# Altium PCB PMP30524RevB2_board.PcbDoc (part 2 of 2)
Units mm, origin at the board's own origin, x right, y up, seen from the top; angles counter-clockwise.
Board outline 60.96 x 53.34 mm, 2 copper layers (Top Layer, Bottom Layer), stack 1.575 mm thick; 66 components, 30 nets, 147 pads, 87 vias.
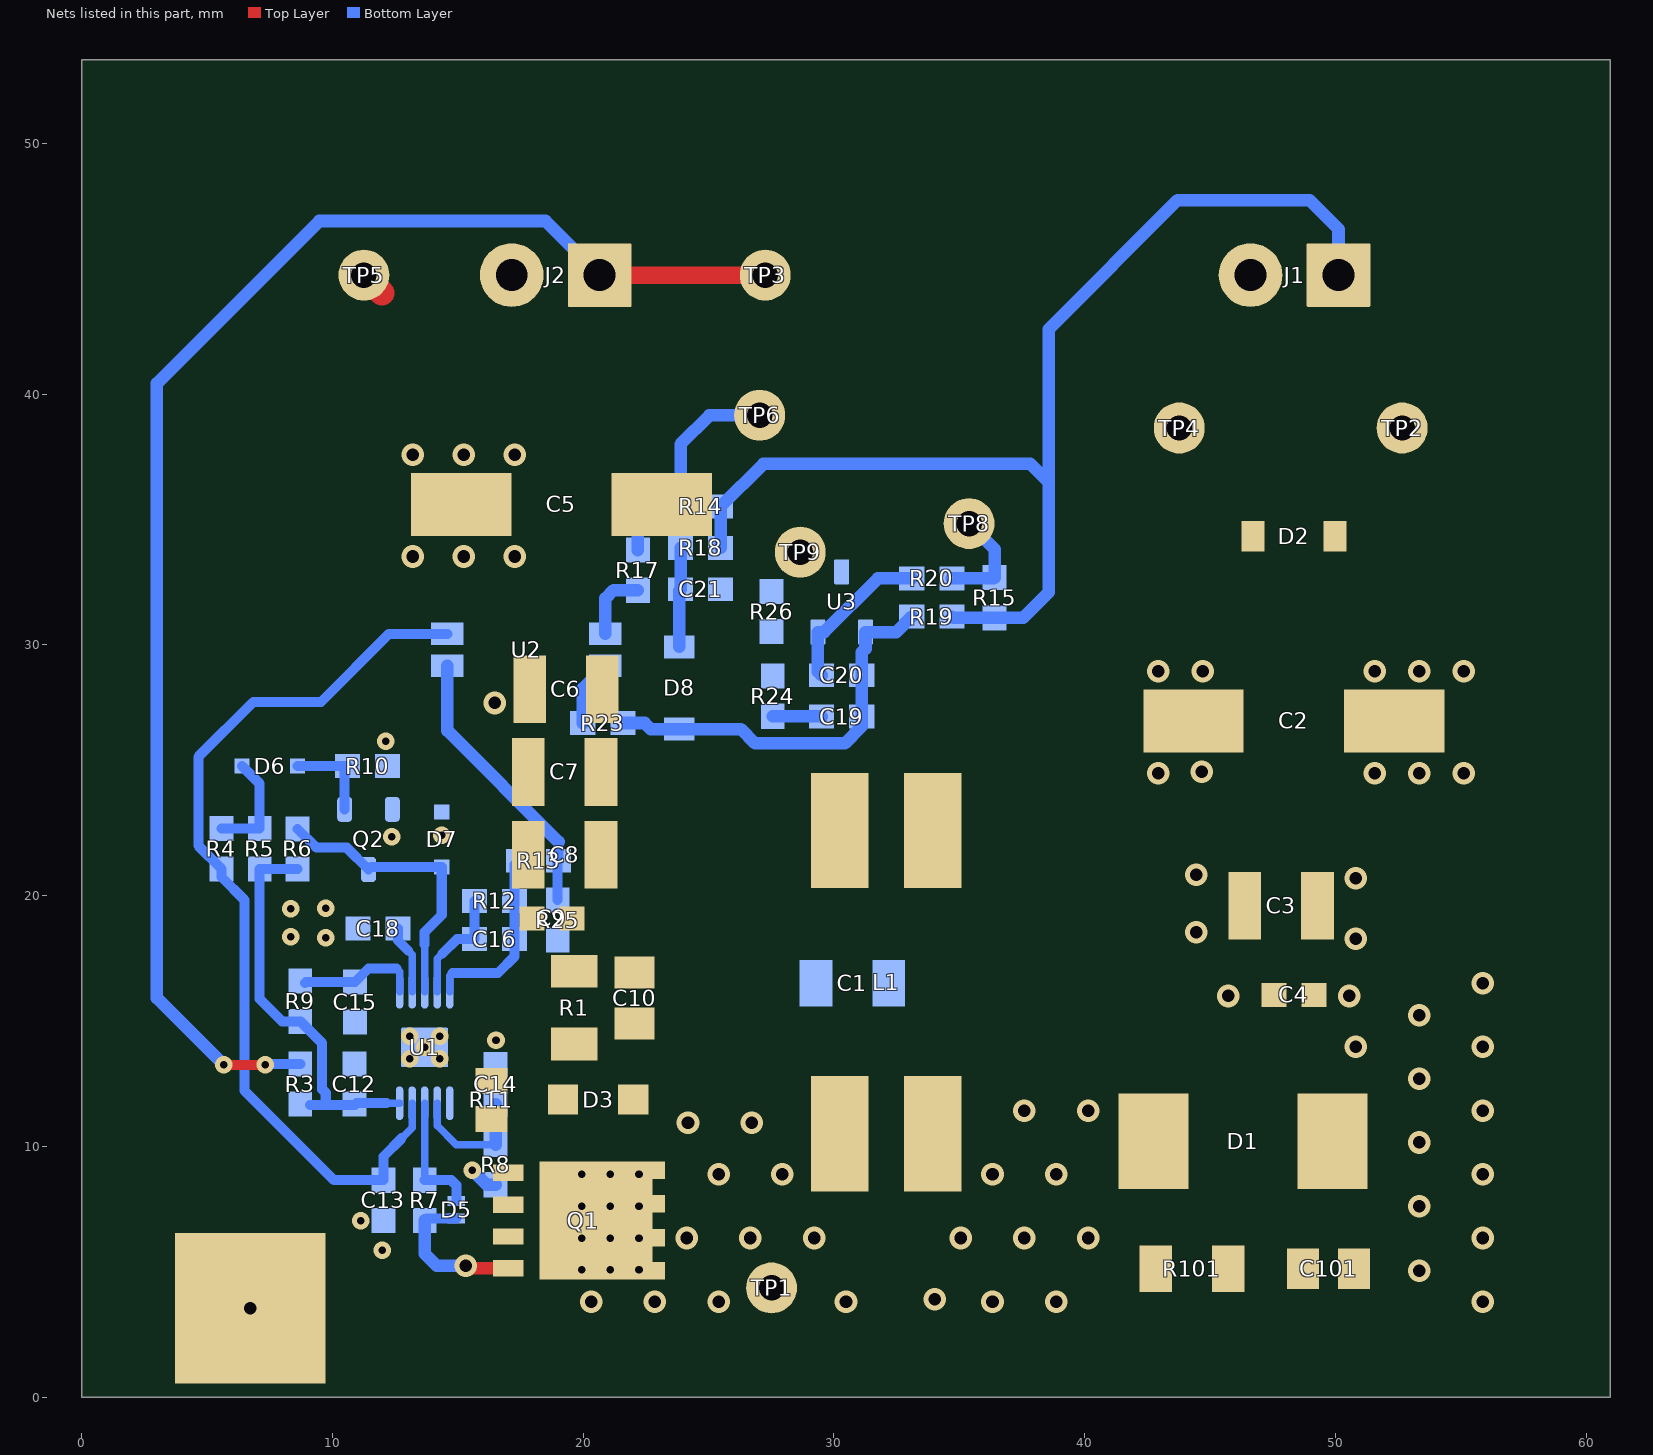
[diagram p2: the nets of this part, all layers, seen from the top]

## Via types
v1: diameter 0.9, hole 0.5, Top Layer to Bottom Layer, 28 vias
v2: diameter 0.9, hole 0.5, Top Layer to Bottom Layer, tented top, 27 vias
v3: diameter 0.7, hole 0.3, Top Layer to Bottom Layer, 20 vias
v4: diameter 0.7, hole 0.3, Top Layer to Bottom Layer, tented bottom, 10 vias
v5: diameter 0.9, hole 0.5, Top Layer to Bottom Layer, tented bottom, 2 vias

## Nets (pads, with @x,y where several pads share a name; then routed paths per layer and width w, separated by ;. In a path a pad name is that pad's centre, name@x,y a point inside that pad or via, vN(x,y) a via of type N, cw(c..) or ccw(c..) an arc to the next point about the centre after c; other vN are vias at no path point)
GND: C1.2 C5.2 C6.2 C7.2 C8.2 C9.2 C12.2 C13.2 C14.2 C15.2 C18.2 D7.2 J2.2 pad.1 Q2.2 R10.1 R11.1 R25.1 TP5.1 U1.6 U1.11 | length 1
  Top Layer w1: TP5.1@11.257,44.748 TP5.1@11.972,44.033
  other v1: 16.466,27.686 13.208,33.528 13.208,37.592 15.24,37.592 17.272,37.592
  other v3: 11.985,5.857 13.078,13.501 14.278,13.501 13.678,13.951 13.078,14.401 14.278,14.401
  other v4: 11.13,7.044 16.522,14.242 9.733,18.332 8.336,18.369 8.337,19.474 9.733,19.506 12.37,22.348 14.36,22.415 12.135,26.162
  other v5: 15.24,33.528 17.272,33.528
GND2: C1.1 C2.2 C3.2 C4.2 C21.2 D2.2 J1.2 L1.4 R26.1 TP4.1 TP9.1 U3.3
  other v1: 45.72,16.002 44.45,18.542 44.45,20.828
  other v2: 42.926,24.892 44.658,24.936 42.926,28.956 44.704,28.956
NetC5_1: C5.1 C6.1 C7.1 C8.1 C9.1 C10.1 J2.1 L1.3 R1.2 R3.2 TP3.1 | length 59.2
  Top Layer w0.4: v3(5.669,13.252) v4(7.32,13.252)
  Top Layer w0.7: J2.1@20.655,44.748 TP3.1@27.259,44.748
  Bottom Layer w0.4: v4(7.32,13.252) 7.358,13.29 R3.2@8.717,13.29
  Bottom Layer w0.5: v3(5.669,13.252) 3.002,15.919 3.002,40.43 9.479,46.907 18.496,46.907 J2.1@20.655,44.748
NetC10_2: C10.2 D3.1 R1.1
NetC12_1: C12.1 R3.1 R5.2 R6.2 R9.2 U1.10 | length 16
  Bottom Layer w0.3: 12.148,11.726 U1.10@12.678,11.726
  Bottom Layer w0.4: R6.2@8.611,21.065 8.603,21.073 R5.2@7.099,21.073 7.099,15.886 7.993,14.992 R9.2@8.717,14.992 9.592,14.117 9.592,12.283 9.733,12.142 9.733,11.66 ; R3.1@9.114,11.66 9.733,11.66 ; 12.148,11.726 10.958,11.726 10.892,11.66 9.733,11.66
NetC14_1: C14.1 R8.1 U1.7 | length 5.1
  Bottom Layer w0.3: U1.7@14.178,11.726 14.178,10.836 14.942,10.073 R8.1@16.506,10.073
  Bottom Layer w0.5: R8.1@16.506,10.073 C14.1@16.506,11.676
NetC15_1: C15.1 R9.1 U1.1 | length 4.9
  Bottom Layer w0.3: 12.549,17.101 12.678,16.972 U1.1@12.678,16.176
  Bottom Layer w0.4: R9.1@8.906,16.524 8.944,16.562 C15.1@10.9,16.562 11.439,17.101 12.549,17.101
NetC16_1: C16.1 R12.2 U1.4 | length 4.6
  Bottom Layer w0.3: U1.4@14.178,16.176 14.178,17.482 14.393,17.697
  Bottom Layer w0.4: 14.393,17.697 14.965,18.269 C16.1@15.666,18.269 R12.2@15.666,19.793
NetC16_2: C16.2 R12.1 R13.2 U1.5 | length 7.4
  Bottom Layer w0.3: U1.5@14.678,16.176 14.678,16.808 14.786,16.915
  Bottom Layer w0.4: 14.786,16.915 16.598,16.915 17.266,17.584 C16.2@17.266,18.269 R12.1@17.266,19.793 17.266,21.236 R13.2@17.422,21.393
NetC18_1: C18.1 U1.2 | length 2.7
  Bottom Layer w0.3: 13.018,17.815 13.178,17.654 U1.2@13.178,16.176
  Bottom Layer w0.4: C18.1@12.62,18.69 12.62,18.213 13.018,17.815
NetC19_1: C19.1 R24.1 | length 2
  Bottom Layer w0.5: R24.1@27.555,27.156 29.493,27.156 C19.1@29.507,27.141
NetC19_2: C19.2 C20.1 D8.2 R19.1 R23.1 U3.1 | length 16.1
  Bottom Layer w0.5: R23.1@21.582,26.887 22.45,26.887 22.691,26.646 D8.2@23.83,26.646 26.285,26.646 26.853,26.079 30.434,26.079 31.107,26.752 C19.2@31.107,27.141 C20.1@31.107,28.792 31.107,29.699 31.257,29.849 U3.1@31.257,30.513 32.486,30.513 R19.1@33.101,31.129
NetC20_2: C20.2 R20.1 R24.2 R26.2 U3.2 | length 6.4
  Bottom Layer w0.5: C20.2@29.507,28.792 29.357,28.942 U3.2@29.357,30.513 29.607,30.513 31.747,32.653 R20.1@33.101,32.653
NetC21_1: C21.1 D8.1 R18.1 | length 4
  Bottom Layer w0.5: D8.1@23.83,29.921 23.83,32.17 C21.1@23.881,32.221 R18.1@23.881,33.872
NetC101_2: C101.2 R101.2
NetD1_2: D1.2 L1.2 R101.1
  other v2: 36.322,3.81 38.862,3.81 34.012,3.914 35.052,6.35 37.592,6.35 40.132,6.35 36.322,8.89 38.862,8.89 37.592,11.43 40.132,11.43
NetD3_2: D3.2 L1.1 Q1.5 Q1.6 Q1.7 Q1.8 Q1.9 TP1.1
  other v1: 20.32,3.81 22.86,3.81 25.4,3.81 24.13,6.35
  other v2: 30.48,3.81 26.67,6.35 29.21,6.35 25.4,8.89 27.94,8.89 24.179,10.949 26.719,10.949
  other v3: 19.939,5.08 21.082,5.08 22.225,5.08 19.939,6.35 21.082,6.35 22.225,6.35 19.939,7.62 21.082,7.62 22.225,7.62 19.939,8.89 21.082,8.89 22.225,8.89
NetD5_1: D5.1 R7.2 U1.8 | length 5
  Bottom Layer w0.3: R7.2@13.678,8.655 U1.8@13.678,11.726
  Bottom Layer w0.4: R7.2@13.678,8.655 14.74,8.655 14.94,8.455 D5.1@14.94,7.834
NetD5_2: D5.2 Q1.4 R7.1 | length 6.2
  Top Layer w0.5: v1(15.321,5.251) 15.433,5.139 Q1.4@17.01,5.139
  Bottom Layer w0.4: R7.1@13.678,7.055 13.757,7.134 D5.2@14.94,7.134
  Bottom Layer w0.5: R7.1@13.678,7.055 13.678,5.726 14.153,5.251 v1(15.321,5.251)
NetD6_1: D6.1 R4.1 R5.1 | length 4.3
  Bottom Layer w0.4: R4.1@5.575,22.673 R5.1@7.099,22.673 7.099,24.47 D6.1@6.402,25.167
NetD6_2: D6.2 Q2.1 R10.2 | length 3.8
  Bottom Layer w0.4: D6.2@8.602,25.167 R10.2@10.601,25.167 10.489,25.054 Q2.1@10.489,23.446
NetD7_1: D7.1 Q2.3 R6.1 U1.3 | length 11.7
  Bottom Layer w0.3: U1.3@13.678,16.176 13.678,18.059
  Bottom Layer w0.4: R6.1@8.611,22.665 9.362,21.914 10.571,21.914 Q2.3@11.439,21.046 11.539,21.146 D7.1@14.36,21.146 14.36,19.236 13.678,18.554 13.678,18.059
NetQ1_1: Q1.1 Q1.2 Q1.3 R8.2 R11.2 | length 1.2
  Bottom Layer w0.5: v3(15.575,9.061) 16.163,8.473 R8.2@16.506,8.473
NetR13_1: R13.1 R25.2 U2.3 | length 11.2
  Bottom Layer w0.4: R25.2@18.984,19.831 18.984,21.355 R13.1@19.022,21.393 19.022,22.15
  Bottom Layer w0.5: U2.3@14.584,29.173 14.584,26.589 19.022,22.15
NetR14_1: R14.1 R17.2 TP6.1 | length 9.2
  Bottom Layer w0.5: R17.2@22.183,33.783 22.183,34.995 22.711,35.523 R14.1@23.881,35.523 23.881,38.004 25.037,39.16 TP6.1@27.038,39.16
NetR15_2: R15.2 R20.2 TP8.1 | length 4.3
  Bottom Layer w0.5: R20.2@34.701,32.653 36.374,32.653 R15.2@36.403,32.682 36.403,33.826 TP8.1@35.387,34.842
NetR17_1: R17.1 U2.1 | length 2.8
  Bottom Layer w0.5: U2.1@20.884,30.443 20.884,31.858 21.209,32.183 R17.1@22.183,32.183
NetR23_2: R23.2 U2.2 | length 2.7
  Bottom Layer w0.5: R23.2@19.982,26.887 19.982,28.271 U2.2@20.884,29.173
VBP: C13.1 R4.2 U1.9 U2.4 | length 36.6
  Bottom Layer w0.3: 12.76,10.331 13.178,10.749 U1.9@13.178,11.726
  Bottom Layer w0.4: 12.76,10.331 12.035,9.606 C13.1@12.035,8.655 10.064,8.655 6.487,12.231 6.487,19.836 5.575,20.748 R4.2@5.575,21.073 4.653,21.994 4.653,25.538 6.845,27.73 9.546,27.73 12.259,30.443 U2.4@14.584,30.443
VOUT: C2.1 C3.1 C4.1 C101.1 D1.1 D2.1 J1.1 R14.2 R15.1 R18.2 R19.2 TP2.1 | length 46.5
  Bottom Layer w0.5: R18.2@25.481,33.872 R14.2@25.481,35.523 27.182,37.223 37.832,37.223 38.562,36.493 ; R19.2@34.701,31.129 34.748,31.082 R15.1@36.403,31.082 37.546,31.082 38.562,32.098 38.562,36.493 ; J1.1@50.119,44.748 50.119,46.58 48.964,47.735 43.708,47.735 38.562,42.589 38.562,36.493
  other v1: 55.88,3.81 53.34,5.044 55.88,6.35 53.34,7.62 55.88,8.89 53.34,10.16 55.88,11.43 53.34,12.7 50.8,13.97 55.88,13.97 53.34,15.24 50.546,16.002 55.88,16.51 50.8,18.288 50.8,20.701
  other v2: 51.562,24.892 53.34,24.892 55.118,24.892 51.562,28.956 53.34,28.956 55.118,28.956

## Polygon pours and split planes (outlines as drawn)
GND on Top Layer "TOP_LAYER_GND_P034" (solid, remove dead copper, pour order 34): 14.292,12.142 12.654,10.504 12.654,6.544 14.836,4.362 17.611,4.362 17.611,2.544 17.016,1.949 6.717,1.949 4.272,4.394 4.272,42.788 9.951,48.467 14.278,44.14 14.278,13.501
GND on Top Layer "TOP_LAYER_GND_P030" (solid, remove dead copper, pour order 30): 13.416,46.018
VOUT on Top Layer "TOP_LAYER_VOUT_P028" (solid, remove dead copper, pour order 28): 50.119,2.042 50.119,5.982 48.468,7.633 48.468,48.514 55.118,48.514 57.358,46.274 57.358,2.675 56.668,1.984
NetC101_2 on Top Layer "TOP_LAYER_NETC101_2_P026" (solid, remove dead copper, pour order 26): 50.246,2.965
NetC101_2 on Top Layer "TOP_LAYER_NETC101_2_P024" (solid, remove dead copper, pour order 24): 44.912,6.013 44.912,3.65 ccw(c46.614,3.65) 46.614,1.949 47.579,1.949 ccw(c47.579,3.727) 49.357,3.727 49.357,5.98 ccw(c48.816,5.98) 48.816,6.521 45.42,6.521 ccw(c45.42,6.013)
NetD1_2 on Top Layer "TOP_LAYER_NETD1_2_P022" (solid, remove dead copper, pour order 22): 32.72,12.617 32.72,4.489 ccw(c35.26,4.489) 35.26,1.949 41.737,1.949 ccw(c41.737,4.489) 44.277,4.489 44.277,11.845 ccw(c43.388,11.845) 43.388,12.734 32.847,12.734 32.847,12.723 32.827,12.723 ccw(c32.827,12.617)
GND2 on Top Layer "TOP_LAYER_GND2_P020" (solid, remove dead copper, pour order 20): 40.975,25.52 40.31,25.52 34.291,31.54 27.05,31.54 26.497,32.092 26.497,34.251 31.025,38.779 31.025,43.732 35.807,48.514 40.975,48.514
GND2 on Top Layer "TOP_LAYER_GND2_P018" (solid, remove dead copper, pour order 18): 42.626,13.252 36.572,13.252 35.928,13.895 30.496,13.895 29.037,15.354 29.037,25.189 29.037,25.19 31.323,25.19 31.372,25.141 31.372,19.553 32.306,18.619 40.848,18.619
GND2 on Top Layer "TOP_LAYER_GND2_P016" (solid, remove dead copper, pour order 16): 47.96,48.514 47.96,13.887 47.325,13.252 40.772,13.252 40.086,13.938 40.086,48.514
GND on Top Layer "TOP_LAYER_GND_P014" (solid, remove dead copper, pour order 14): 17.099,12.109 12.731,12.109 10.025,14.814 10.025,48.558 18.496,48.558 18.496,18.484 18.199,18.186 18.199,13.035
NetQ1_1 on Top Layer "TOP_LAYER_NETQ1_1_P012" (solid, remove dead copper, pour order 12): 17.607,6.013 14.432,6.013 13.289,7.156 13.289,10.655 14.234,11.601 16.972,11.601 17.607,10.966
NetD3_2 on Top Layer "TOP_LAYER_NETD3_2_P010" (solid, remove dead copper, pour order 10): 31.461,12.574 ccw(c31.356,12.574) 31.356,12.679 21.611,12.679 ccw(c21.613,12.304) 21.238,12.303 ccw(c21.92,12.235) 21.234,12.236 cw(c19.012,12.235) 20.584,10.664 20.217,10.298 cw(c19.41,11.104) 19.41,9.964 18.835,9.964 ccw(c18.835,9.302) 18.174,9.302 18.174,4.489 ccw(c20.714,4.489) 20.714,1.949 28.929,1.949 ccw(c28.929,4.489) 31.469,4.489 31.469,12.49 ccw(c31.038,12.489)
NetC10_2 on Top Layer "TOP_LAYER_NETC10_2_P008" (solid, remove dead copper, pour order 8): 18.943,15.596 ccw(c18.943,15.212) 18.559,15.212 18.559,11.16 ccw(c18.877,11.16) 18.877,10.841 19.683,10.841 ccw(c19.683,11.298) 20.139,11.298 20.139,11.644 cw(c20.796,11.644) 20.332,12.109 21.101,12.877 cw(c22.433,11.545) 22.433,13.43 22.708,13.43 ccw(c22.708,14.119) 23.195,13.632 ccw(c22.889,13.938) 23.322,13.938 23.322,15.038 ccw(c22.764,15.038) 22.764,15.596
NetC5_1 on Top Layer "TOP_LAYER_NETC5_1_P006" (solid, remove dead copper, pour order 6): 32.015,26.261 31.831,26.445 31.831,26.448 28.519,26.448 25.344,23.273 25.231,32.429 27.204,30.456 33.423,30.456 36.657,27.222 36.657,21.38 35.69,20.413 32.72,20.413 32.72,25.555
NetC5_1 on Top Layer "TOP_LAYER_NETC5_1_P004" (solid, remove dead copper, pour order 4): 19.385,20.159 19.035,19.809 19.035,18.101 18.623,17.689 18.623,16.3 22.82,16.3 22.82,20.778 25.608,23.566 25.608,46.74 23.834,48.514 19.354,48.514 19.385,44.748
NetC5_1 on Top Layer "TOP_LAYER_NETC5_1_P002" (solid, remove dead copper, pour order 2): 14.178,41.573
VOUT on Bottom Layer "BOTTOM_LAYER_VOUT_P060" (solid, remove dead copper, pour order 60): 50.119,2.042 50.119,5.982 48.468,7.633 48.468,48.514 55.118,48.514 57.358,46.274 57.358,2.675 56.668,1.984
NetD1_2 on Bottom Layer "BOTTOM_LAYER_NETD1_2_P058" (solid, remove dead copper, pour order 58): 32.72,12.617 32.72,4.489 ccw(c35.26,4.489) 35.26,1.949 41.737,1.949 ccw(c41.737,4.489) 44.277,4.489 44.277,11.845 ccw(c43.388,11.845) 43.388,12.734 32.847,12.734 32.847,12.723 32.827,12.723 ccw(c32.827,12.617)
NetD3_2 on Bottom Layer "BOTTOM_LAYER_NETD3_2_P056" (solid, remove dead copper, pour order 56): 21.489,1.949 cw(c21.489,3.978) 19.459,3.978 19.459,9.591 cw(c21.458,9.591) 21.458,11.59 29.609,11.59 cw(c29.596,9.717) 31.469,9.704 31.469,4.489 cw(c28.929,4.489) 28.929,1.949
GND2 on Bottom Layer "BOTTOM_LAYER_GND2_P052" (solid, remove dead copper, pour order 52): 19.311,26.419
NetC20_2 on Bottom Layer "BOTTOM_LAYER_NETC20_2_P050" (solid, remove dead copper, pour order 50): 28.402,29.159
NetC20_2 on Bottom Layer "BOTTOM_LAYER_NETC20_2_P048" (solid, remove dead copper, pour order 48): 34.625,29.267
NetC20_2 on Bottom Layer "BOTTOM_LAYER_NETC20_2_P046" (solid, remove dead copper, pour order 46): 30.18,28.111 30.18,31.129 26.89,31.129 26.89,28.111
GND2 on Bottom Layer "BOTTOM_LAYER_GND2_P044" (solid, remove dead copper, pour order 44): 32.737,13.63 47.386,13.63 48.006,14.088 48.006,48.685 31.025,48.685 31.025,34.805 40.086,25.744 40.086,18.586 32.928,18.586 32.737,18.394
GND2 on Bottom Layer "BOTTOM_LAYER_GND2_P042" (solid, remove dead copper, pour order 42): 24.973,31.54 30.007,31.54 30.815,32.348 30.815,34.292 29.757,35.35 27.603,35.35 26.497,34.244 26.497,32.946 24.973,32.946
GND on Bottom Layer "BOTTOM_LAYER_GND_P040" (solid, remove dead copper, pour order 40): 18.878,3.81 18.878,10.615 20.455,12.192 27.26,12.192 28.685,13.618 28.685,21.223 24.084,25.825 18.509,25.825 18.509,46.78 9.352,46.78 3.637,41.065 3.637,5.029 6.717,1.949 17.016,1.949

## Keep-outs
Keep-Out Layer:
  text ".Layer_Name" at 14.656,-21.806 h1.52

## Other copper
Top Layer:
  text ".Layer_Name" at 14.656,-21.806 h1.52
Bottom Layer:
  pour cut-out: 12.192,15.621 12.192,15.2 12.573,14.819 14.97,14.819 15.239,15.088 15.239,15.651
  pour cut-out: 14.859,12.486
  pour cut-out: 12.135,12.337 12.135,12.703 12.513,13.081 14.097,13.081 14.478,12.7 14.478,12.322
  text ".Layer_Name" at 14.656,-21.806 h1.52

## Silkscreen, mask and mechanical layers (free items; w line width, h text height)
Top Overlay:
  text "GND" at 11.638,47.117 h1
  text "VIN" at 23.749,47.008 h1
  text "GND2" at 39.878,47.008 h1
  text "VOUT" at 53.086,46.99 h1
  text "2018/09" at 59.944,45.974 h1 r90
  text "NWA" at 24.557,40.85 h1
  text "NWA" at 37.084,34.472 h1
  text "GND2" at 27.178,30.879 h1
  text "'.PRJ_Number' '.SCH_Rev'" at 3.302,14.732 h1.85 r90
  text "TPS40210 Flyback" at 59.69,1.397 h1.5 r90
  text ".Layer_Name" at 14.656,-21.806 h1.52
Bottom Overlay:
  text ".Layer_Name" at 14.656,-21.806 h1.52
Top Paste:
  text ".Layer_Name" at 14.656,-21.806 h1.52
Bottom Paste:
  text ".Layer_Name" at 14.656,-21.806 h1.52
Top Solder:
  text ".Layer_Name" at 14.656,-21.806 h1.52
  text ".Layer_Name" at 14.656,-21.806 h1.52
Bottom Solder:
  text "'.PRJ_Number' '.SCH_Rev'" at 47.244,36.576 h1.85 r90
  text ".Layer_Name" at 14.656,-21.806 h1.52
Drill Guide:
  text ".Layer_Name" at 14.656,-21.806 h1.52
M1 Board Outline:
  the board outline again, w0.254
  text ".Layer_Name" at 14.656,-21.806 h1.52
M2 Board Dimensions:
  rectangle: 3.175,-10.16 12.7,-6.985
  rectangle: 0,-6.985 3.175,-3.81
  lines w0.178: 0,-6.985 25.4,-6.985 ; 3.175,-10.16 3.175,-3.81 ; 6.35,-10.16 6.35,-3.81 ; 12.7,-10.16 12.7,-3.81 ; 19.05,-10.16 19.05,-3.81 ; 0,-10.16 0,-3.81 25.4,-3.81 25.4,-10.16 0,-10.16
  text "'.Print_Date'  '.Print_Time'" at 0.762,54.318 h1.85
  text ".Layer_Name" at 14.656,-21.806 h1.52
M3 3D STEP Top:
  text ".Layer_Name" at 14.656,-21.806 h1.52
M4 3D STEP Bottom:
  text ".Layer_Name" at 14.656,-21.806 h1.52
M5 Assembly Top:
  lines w0.254: -7.417,-23.626 160.223,-23.626 ; -7.417,-18.462 160.274,-18.462 ; -7.417,-13.297 -7.417,-28.791 94.31,-28.791 160.274,-28.791 160.274,-13.297 -7.404,-13.297 -7.404,-28.791 32.614,-28.791 ; 55.194,-28.791 55.194,-13.297 ; 87.376,-18.462 87.376,-13.297 ; 108.712,-18.462 108.712,-13.297 ; 124.511,-28.956 124.511,-23.804
  text "COMPONENTS MARKED 'DNP' SHOULD NOT BE POPULATED." at 29.299,-8.09 h1.52
  text "ASSEMBLY VARIANT:" at 29.286,-11.024 h1.52
  text ".VariantName" at 55.601,-11.024 h1.52
  text "PCB VIEWED FROM TOP SIDE" at -5.804,-16.654 h1.52
  text "BOARD #:" at 57.099,-16.654 h1.52
  text ".PRJ_Number" at 70.955,-16.654 h1.52
  text "REV:" at 92.405,-16.654 h1.52
  text ".PCB_Rev" at 99.809,-16.654 h1.52
  text "SVN REV:" at 113.69,-16.654 h1.52
  text ".VersionControl_RevNumber" at 126.543,-16.654 h1.52
  text "TID #:" at 57.099,-21.819 h1.52
  text ".TID" at 70.955,-21.819 h1.52
  text "PLOT NAME =" at -5.804,-27.034 h1.52
  text ".plot_File_Name" at 14.656,-27.034 h1.52
  text "GENERATED    :" at 57.15,-27.034 h1.52
  text ".Print_Date" at 79.235,-27.034 h1.52
  text ".Print_Time" at 97.752,-27.034 h1.52
  text "TEXAS INSTRUMENTS" at 129.87,-27.034 h1.52
M6 Assembly Bottom:
  lines w0.254: -7.429,-18.474 160.261,-18.474 ; -7.379,-23.639 160.261,-23.639 ; 28.334,-28.969 28.334,-23.817 ; 44.133,-18.474 44.133,-13.31 ; 65.468,-18.474 65.468,-13.31 ; 97.65,-28.804 97.65,-13.31 ; 120.231,-28.804 160.249,-28.804 160.249,-13.31 -7.429,-13.31 -7.429,-28.804 58.534,-28.804 160.261,-28.804 160.261,-13.31
  text "COMPONENTS MARKED 'DNP' SHOULD NOT BE POPULATED." at 154.991,-8.077 h1.52
  text ".VariantName" at 128.473,-11.024 h1.52
  text "ASSEMBLY VARIANT:" at 154.864,-11.024 h1.52
  text ".VersionControl_RevNumber" at 26.302,-16.667 h1.52
  text "SVN REV:" at 39.154,-16.667 h1.52
  text ".PCB_Rev" at 53.035,-16.667 h1.52
  text "REV:" at 60.439,-16.667 h1.52
  text ".PRJ_Number" at 81.89,-16.667 h1.52
  text "BOARD #:" at 95.745,-16.667 h1.52
  text "PCB VIEWED FROM BOTTOM SIDE" at 158.648,-16.667 h1.52
  text ".TID" at 81.89,-21.831 h1.52
  text "TID #:" at 95.745,-21.831 h1.52
  text "TEXAS INSTRUMENTS" at 22.974,-27.047 h1.52
  text ".Print_Time" at 55.093,-27.047 h1.52
  text ".Print_Date" at 73.609,-27.047 h1.52
  text "GENERATED    :" at 95.694,-27.047 h1.52
  text ".plot_File_Name" at 138.189,-27.047 h1.52
  text "PLOT NAME =" at 158.648,-27.047 h1.52
M9 Title Sheet:
  drawing of 57 lines, arcs and shapes, not listed
  text "1" at 18.792,204.127 h1.78
  text "2" at 82.182,204.127 h1.78
  text "3" at 145.411,204.127 h1.78
  text "4" at 209.08,204.127 h1.78
  text "5" at 272.555,204.127 h1.78
  text "6" at 336.182,204.127 h1.78
  text "A" at -10.579,175.095 h1.78
  text "A" at 365.341,175.095 h1.78
  text "B" at -10.579,114.643 h1.78
  text "B" at 365.341,114.643 h1.78
  text "C" at -10.579,54.318 h1.78
  text "C" at 365.341,54.318 h1.78
  text "PROJECT TITLE:" at 288.125,7.048 h1.14
  text ".PRJ_Title" at 289.395,3.662 h1.78
  text "DESIGNED FOR:" at 288.125,-0.597 h1.14
  text ".PRJ_Customer" at 289.395,-4.153 h1.78
  text "D" at -10.579,-5.88 h1.78
  text "D" at 365.341,-5.88 h1.78
  text "FILE NAME:" at 288.125,-8.217 h1.14
  text ".PCB_File_Name_No_Path" at 289.395,-11.265 h1.78
  text "Texas Instruments (TI) and/or its licensors do not warrant the accuracy or completeness of this specification" at 161.9,-15.376 h1.14
  text "ENGINEER:" at 288.125,-15.583 h1.14
  text "LAYOUT BY:" at 326.352,-15.583 h1.14
  text "or any information contained therein. TI and/or its licensors do not warrant that this design will meet" at 160.757,-18.237 h1.14
  text ".PRJ_Engineer" at 289.395,-19.52 h1.78
  text ".PCB_Layout" at 327.635,-19.52 h1.78
  text "the specifications, will be suitable for your application or fit for any particular purpose, or will operate in" at 160.757,-21.099 h1.14
  text ".Layer_Name" at 14.656,-21.806 h1.52
  text "ALTIUM DESIGNER VERSION:" at 326.352,-23.457 h1.14
  text "an implementation. TI and/or its licensors do not warrant that the design is production worthy. You should" at 160.757,-23.961 h1.14
  text "completely validate and test your design implementation to confirm the system functionality for your application." at 161.9,-26.822 h1.14
  text ".print_Scale" at 289.395,-26.843 h1.78
  text ".Application_BuildNumber" at 327.635,-26.843 h1.78
  text "1" at 18.792,-32.093 h1.78
  text "2" at 82.182,-32.093 h1.78
  text "3" at 145.411,-32.093 h1.78
  text "4" at 209.08,-32.093 h1.78
  text "5" at 272.555,-32.093 h1.78
  text "6" at 336.182,-32.093 h1.78
M10 Fab Notes:
  drawing of 189 lines, arcs and shapes, not listed
  text "DESIGN INFORMATION" at 314.503,161.447 h1.52
  text "MIN. TRACK WIDTH:" at 298.131,158.091 h1.52
  text "8" at 325.976,158.091 h1.52
  text "MIL" at 329.907,158.091 h1.52
  text "MIN. CLEARANCE:" at 298.131,154.938 h1.52
  text "0.2" at 324.452,154.938 h1.52
  text "mm" at 329.907,154.938 h1.52
  text "MIN. VIA PAD SIZE:" at 298.131,151.785 h1.52
  text "24" at 325.214,151.785 h1.52
  text "MIL" at 329.907,151.785 h1.52
  text "0.05mm (2MIL)" at 315.784,148.486 h1.52
  text "MINIMUM ANNULAR RING" at 289.769,148.277 h1.52
  text "EXTERNAL" at 333.768,148.277 h1.52
  text "PER" at 294.849,145.48 h1.52
  text "IPC-D-275 CLASS 2 LEVEL C" at 300.437,145.48 h1.52
  text "MIL, HOLES" at 338.238,142.928 h1.52
  text "+/-" at 328.27,142.709 h1.52
  text "+/-" at 349.961,142.709 h1.52
  text "REGISTRATION TOLERANCES:" at 289.769,142.682 h1.52
  text "METAL" at 320.243,142.682 h1.52
  text "5" at 334.879,142.683 h1.52
  text "3" at 356.037,142.683 h1.52
  text "MIL" at 358.99,142.682 h1.52
  text "HOLE SIZE TOLERANCE (UNLESS OTHERWISE SPECIFIED):" at 289.769,140.185 h1.52
  text "+/-" at 349.961,140.112 h1.52
  text "3" at 356.037,140.085 h1.52
  text "MIL" at 358.99,140.085 h1.52
  text "MATERIAL:" at 287.87,136.589 h1.52
  text "FR-4 High Tg" at 312.926,133.324 h1.52
  text "X" at 309.257,133.122 h1.52
  text "FR-408" at 298.563,133.007 h1.52
  text "OTHER" at 336.358,133.007 h1.52
  text "62 MIL (1.6mm) +/-10%" at 306.694,129.374 h1.52
  text "X" at 303.643,129.312 h1.52
  text "THICKNESS:" at 289.769,129.165 h1.52
  text "OTHER" at 339.33,129.165 h1.52
  text "TOLERANCE:" at 289.769,125.652 h1.52
  text "X" at 311.314,125.652 h1.52
  text "ANSI IPC-6012 TYPE 3 CLASS 2" at 315.836,125.652 h1.52
  text "OTHER +/-" at 315.835,121.989 h1.52
  text "BOW & TWIST:" at 289.769,118.302 h1.52
  text "X" at 311.314,118.302 h1.52
  text "ANSI IPC-6012 TYPE 3 CLASS 2" at 315.836,118.302 h1.52
  text "OTHER +/-" at 315.835,114.576 h1.52
  text "DRILLING:" at 287.87,111.258 h1.52
  text "NC_DRILL FILES" at 332.599,108.586 h1.52
  text "REFERENCE:" at 289.769,108.486 h1.52
  text "X" at 306.463,108.484 h1.52
  text "AS SHOWN" at 310.984,108.486 h1.52
  text "X" at 329.348,108.486 h1.52
  text "OTHER" at 340.168,104.873 h1.52
  text "PTH COPPER THICKNESS:" at 289.761,104.783 h1.52
  text "X" at 318.697,104.783 h1.52
  text "20-30 um" at 321.948,104.783 h1.52
  text "BOARD FINISH:" at 287.87,101.034 h1.52
  text "SILKSCREEN:" at 291.812,98.237 h1.52
  text "X" at 316.14,98.237 h1.52
  text "TOP" at 319.112,98.237 h1.52
  text "X" at 329.094,98.237 h1.52
  text "BOTTOM" at 332.091,98.237 h1.52
  text "SILKSCREEN COLOR:" at 291.812,94.295 h1.52
  text "X" at 316.115,94.295 h1.52
  text "WHITE" at 319.112,94.295 h1.52
  text "OTHER" at 332.091,94.295 h1.52
  text "X" at 319.442,90.652 h1.52
  text "GREEN" at 322.439,90.652 h1.52
  text "OTHER" at 338.136,90.652 h1.52
  text "SOLDER RESIST COLOR:" at 291.812,90.477 h1.52
  text "X" at 319.442,86.734 h1.52
  text "MATTE" at 322.439,86.734 h1.52
  text "SEMI-GLOSS" at 338.125,86.717 h1.52
  text "IMMERSION GOLD (ENIG)" at 314.819,82.345 h1.52
  text "ENEPIG" at 348.793,82.162 h1.52
  text "SURFACE FINISH:" at 287.87,82.136 h1.52
  text "X" at 310.298,82.136 h1.52
  text "IMM. TIN/SILVER OR EQUIV" at 296.24,78.649 h1.52
  text "OTHER" at 332.599,78.549 h1.52
  text "ARRAY/PANEL:" at 287.87,74.602 h1.52
  text "CUT AND TRIM PER M1 BOARD OUTLINE" at 314.819,74.393 h1.52
  text "N.C. ROUTE" at 314.819,70.94 h1.52
  text "X" at 332.295,70.94 h1.52
  text "V. SCORE" at 336.816,70.94 h1.52
  text "CERTIFICATION:" at 287.87,67.66 h1.52
  text "MATERIALS AND WORKMANSHIP FOR ALL PCBS" at 306.285,67.66 h1.52
  text "TO MEET OR EXCEED THE REQUIREMENTS OF:" at 306.285,65.271 h1.52
  text "X" at 297.078,62.003 h1.52
  text "ANSI IPC-A-600F CLASS ->" at 300.329,62.003 h1.52
  text "X" at 342.188,62.003 h1.52
  text "2" at 344.982,62.003 h1.52
  text "1" at 336.981,61.965 h1.52
  text "3" at 353.973,61.965 h1.52
  text "X" at 317.702,58.252 h1.52
  text "RoHS" at 320.953,58.252 h1.52
  text "OTHER" at 337.321,58.252 h1.52
  text "PER ORDER" at 347.407,58.252 h1.52
  text "ALL BOARDS MUST MEET OR EXCEED UL94-V0 REQUIREMENTS." at 288.569,54.345 h1.52
  text "PCB MUST BEAR THE UL94V-0 UL REGISTERED MATERIAL ID NUMBER" at 288.569,51.397 h1.52
  text "ADDITIONAL REQUIREMENTS:" at 287.87,47.094 h1.52
  text "MICROSECTION:" at 289.769,44.373 h1.52
  text "YES" at 312.775,44.373 h1.52
  text "REQUIRED" at 334.657,40.707 h1.52
  text "BARE BOARD ELEC. TEST:" at 289.769,40.634 h1.52
  text "NONE" at 322.935,40.634 h1.52
  text "X" at 331.66,40.634 h1.52
  text "PER ORDER" at 349.693,40.634 h1.52
  text "XX MIL VIAS REQUIRE NON-CONDUCTIVE FILL AND PLANARIZE" at 294.04,35.428 h1.5
  text "XX MIL VIAS REQUIRE CONDUCTIVE FILL AND PLANARIZE" at 294.243,32.787 h1.52
  text "OUTER XX MIL VIAS REQUIRE 50 OHM SINGLE-ENDED IMPEDANCE" at 294.218,28.637 h1.47
  text "LAYER 2 & 3 (INNER LAYERS) XX MIL WIDE, XX MIL SPACE / TRACES REQUIRE 100 OHM DIFFERENTIAL IMPEDANCE" at 294.015,22.65 h1.52
  text ".Layer_Name" at 152.927,8.535 h1.52
  text ".Layer_Name" at 14.656,-21.806 h1.52
M11 Gerber Information:
  lines w0.254: -7.417,-23.626 160.223,-23.626 ; -7.417,-18.462 160.274,-18.462 ; -7.417,-13.297 -7.417,-28.791 94.31,-28.791 160.274,-28.791 160.274,-13.297 -7.404,-13.297 -7.404,-28.791 32.614,-28.791 ; 55.194,-28.791 55.194,-13.297 ; 87.376,-18.462 87.376,-13.297 ; 108.712,-18.462 108.712,-13.297 ; 124.511,-28.956 124.511,-23.804
  text "ALL ARTWORK VIEWED FROM TOP SIDE" at -5.804,-16.654 h1.52
  text "BOARD #:" at 57.099,-16.654 h1.52
  text ".PRJ_Number" at 70.955,-16.654 h1.52
  text "REV:" at 92.405,-16.654 h1.52
  text ".PCB_Rev" at 99.809,-16.654 h1.52
  text "SVN REV:" at 113.69,-16.654 h1.52
  text ".VersionControl_RevNumber" at 126.543,-16.654 h1.52
  text "LAYER NAME =" at -5.804,-21.806 h1.52
  text "TID #:" at 57.099,-21.819 h1.52
  text ".TID" at 70.955,-21.819 h1.52
  text "PLOT NAME =" at -5.804,-27.034 h1.52
  text ".plot_File_Name" at 14.656,-27.034 h1.52
  text "GENERATED    :" at 57.15,-27.034 h1.52
  text ".Print_Date" at 79.235,-27.034 h1.52
  text ".Print_Time" at 97.752,-27.034 h1.52
  text "TEXAS INSTRUMENTS" at 129.87,-27.034 h1.52
M12 Stackup:
  drawing of 191 lines, arcs and shapes, not listed
  text "Layer" at 248.865,196.596 h1.52
  text "Name" at 259.277,196.596 h1.52
  text "Material" at 282.892,196.596 h1.52
  text "Thickness" at 304.731,196.596 h1.52
  text "Constant" at 321.236,196.596 h1.52
  text "Board Layer Stack" at 335.711,196.596 h1.52
  text "1" at 248.865,193.548 h1.52
  text "Top Overlay" at 259.277,193.548 h1.52
  text "2" at 248.865,190.5 h1.52
  text "Top Solder" at 259.277,190.5 h1.52
  text "Solder Resist" at 282.892,190.5 h1.52
  text "0.40mil" at 304.731,190.5 h1.52
  text "3.5" at 321.236,190.5 h1.52
  text "3" at 248.865,187.452 h1.52
  text "Top Layer" at 259.277,187.452 h1.52
  text "Copper" at 282.892,187.452 h1.52
  text "1.40mil" at 304.731,187.452 h1.52
  text "4" at 248.865,184.404 h1.52
  text "Dielectric1" at 259.277,184.404 h1.52
  text "FR-4" at 282.892,184.404 h1.52
  text "59.20mil" at 304.731,184.404 h1.52
  text "4.8" at 321.236,184.404 h1.52
  text "5" at 248.865,181.356 h1.52
  text "Bottom Layer" at 259.277,181.356 h1.52
  text "Copper" at 282.892,181.356 h1.52
  text "1.40mil" at 304.731,181.356 h1.52
  text "6" at 248.865,178.308 h1.52
  text "Bottom Solder" at 259.277,178.308 h1.52
  text "Solder Resist" at 282.892,178.308 h1.52
  text "0.40mil" at 304.731,178.308 h1.52
  text "3.5" at 321.236,178.308 h1.52
  text "7" at 248.865,175.26 h1.52
  text "Bottom Overlay" at 259.277,175.26 h1.52
  text ".Layer_Name" at 14.656,-21.806 h1.52
M13 Component Bodies Top:
  text ".Layer_Name" at 14.656,-21.806 h1.52
M14 Component Bodies Bottom:
  text ".Layer_Name" at 14.656,-21.806 h1.52
M15 Courtyards Top:
  text ".Layer_Name" at 14.656,-21.806 h1.52
M16 Courtyards Bottom:
  text ".Layer_Name" at 14.656,-21.806 h1.52
Drill Drawing:
  circle w0.254: c136.241,77.398 r0.703
  lines w0.254: 135.538,73.534 136.943,73.534 136.943,74.939 135.538,74.939 135.538,73.534 ; 135.538,79.857 136.241,80.208 136.943,79.857 136.592,80.559 136.943,81.262 136.241,80.91 135.538,81.262 135.889,80.559 135.538,79.857 ; 135.538,83.369 135.889,83.369 136.241,83.018 136.592,83.369 136.943,83.369 136.592,83.72 136.943,84.072 136.592,84.072 136.241,84.423 135.889,84.072 135.538,84.072 135.889,83.72 135.538,83.369
  lines w0.305: 134.264,72.586 216.377,72.586 ; 134.264,85.231 216.377,85.231 ; 142.854,69.424 142.854,88.392 ; 151.29,69.424 151.29,88.392 ; 167.469,69.424 167.469,88.392 ; 174.057,69.424 174.057,88.392 ; 183.593,69.424 183.593,88.392 ; 201.978,69.424 201.978,88.392 ; 134.264,69.424 216.377,69.424 216.377,88.392 134.264,88.392 134.264,69.424
  text "Symbol" at 136.161,86.179 h1.83
  text "Quantity" at 143.802,86.179 h1.83
  text "Finished Hole Size" at 152.238,86.179 h1.83
  text "Plated" at 168.418,86.179 h1.83
  text "Hole Type" at 175.005,86.179 h1.83
  text "Drill Layer Pair" at 184.541,86.179 h1.83
  text "Hole Tolerance" at 202.927,86.179 h1.83
  text "30" at 143.802,83.018 h1.52
  text "11.81mil (0.300mm)" at 152.238,83.018 h1.52
  text "PTH" at 168.418,83.018 h1.52
  text "Round" at 175.005,83.018 h1.52
  text "Top Layer - Bottom Layer" at 184.541,83.018 h1.52
  text "58" at 143.802,79.857 h1.52
  text "19.69mil (0.500mm)" at 152.238,79.857 h1.52
  text "PTH" at 168.418,79.857 h1.52
  text "Round" at 175.005,79.857 h1.52
  text "Top Layer - Bottom Layer" at 184.541,79.857 h1.52
  text "8" at 143.802,76.695 h1.52
  text "40.00mil (1.016mm)" at 152.238,76.695 h1.52
  text "PTH" at 168.418,76.695 h1.52
  text "Round" at 175.005,76.695 h1.52
  text "Top Layer - Bottom Layer" at 184.541,76.695 h1.52
  text "4" at 143.802,73.534 h1.52
  text "50.00mil (1.270mm)" at 152.238,73.534 h1.52
  text "PTH" at 168.418,73.534 h1.52
  text "Round" at 175.005,73.534 h1.52
  text "Top Layer - Bottom Layer" at 184.541,73.534 h1.52
  text "100 Total" at 143.802,70.373 h1.52
  text ".Layer_Name" at 14.656,-21.806 h1.52
M17 Embedded Cavity:
  text ".Layer_Name" at 14.656,-21.806 h1.52
M18 Embedded Assembly:
  text ".Layer_Name" at 14.656,-21.806 h1.52
M19 Embedded Keepout:
  text ".Layer_Name" at 14.656,-21.806 h1.52

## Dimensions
0,0 to 60.96,0 on M2 Board Dimensions
0,0 to 0,53.34 on M2 Board Dimensions
0,-10.16 to 25.4,-10.16 on M2 Board Dimensions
